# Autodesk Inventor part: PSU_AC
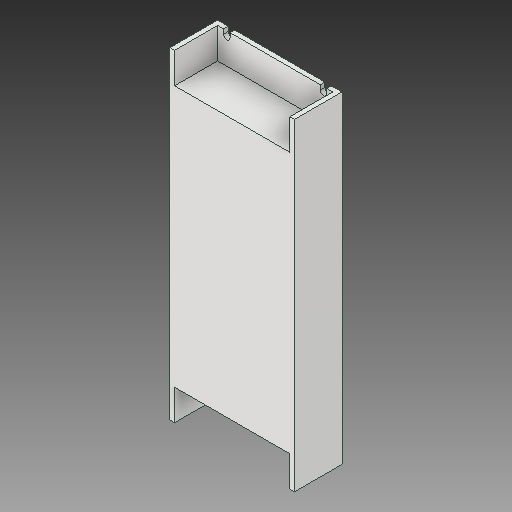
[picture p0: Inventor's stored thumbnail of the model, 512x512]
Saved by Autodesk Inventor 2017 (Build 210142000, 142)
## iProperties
Created: 2017-05
Part Number: PSU_AC
Material: Generic
Document SubType Name: Modeling
Designer: Savy
Density: 1 g/cm^3
Appearance: Default
Author: Savy
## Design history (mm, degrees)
feature "SOLID1"
body "Solid1"
